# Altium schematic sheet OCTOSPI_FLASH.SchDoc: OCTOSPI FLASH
size A4; Date: Not used; ApprovedBy: Not used; CheckedBy: Not used; Author: Not used; CompanyName: STMicroelectronics; DrawnBy: Not used; Engineer: Not used; Organization: Not used; Address1: Not used; Address2: Not used; Address3: Not used; Address4: Not used; DocumentNumber: Not used; Revision: Not used; SheetNumber: 6; SheetTotal: 16
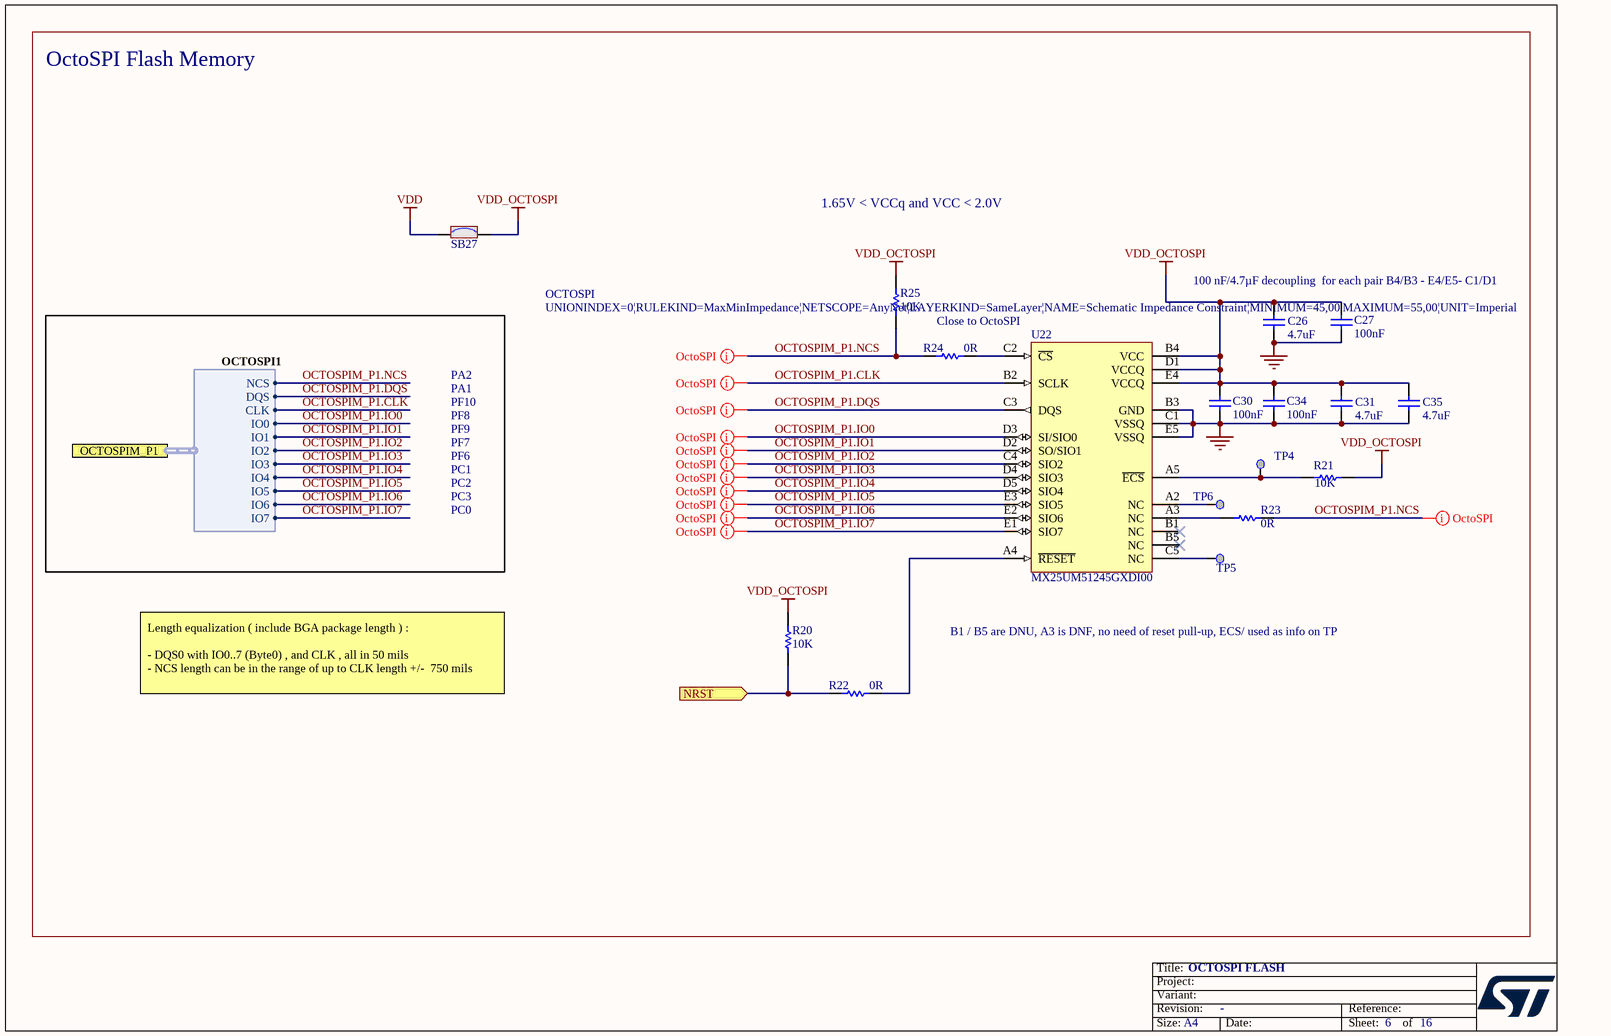
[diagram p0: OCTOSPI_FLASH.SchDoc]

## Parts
C26  value 4.7uF  [C0603]  (hidden comment: Capacitor)
C27  value 100nF  [C0402]  (hidden comment: Capacitor)
C30  value 100nF  [C0402]  (hidden comment: Capacitor)
C31  value 4.7uF  [C0603]  (hidden comment: Capacitor)
C34  value 100nF  [C0402]  (hidden comment: Capacitor)
C35  value 4.7uF  [C0603]  (hidden comment: Capacitor)
R20  value 10K  [R0402]  (hidden comment: Resistor)
R21  value 10K  [R0402]  (hidden comment: Resistor)
R22  value 0R  [R0402]  (hidden comment: Resistor)
R23  value 0R  [R0402]  (hidden comment: Resistor)
R24  value 0R  [R0402]  (hidden comment: Resistor)
R25  value 10K  [R0402]  (hidden comment: Resistor)
SB27  SB_ON  [SOLDER-BRIDGE_R0402-0R]  (value not drawn)
TP4  Test Point  [TP_SMD_1MM]  (value not drawn)  (no BOM)
TP5  Test Point  [TP_SMD_1MM]  (value not drawn)  (no BOM)
TP6  Test Point  [TP_SMD_1MM]  (value not drawn)  (no BOM)
U22  value MX25UM51245GXDI00  [ICC_BGA24_5X5-BALL-ARRAY_6X8_P1]  (hidden comment: MX25xx51245GXDx00)

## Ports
NRST (in), OCTOSPIM_P1 (harness OCTOSPI1)

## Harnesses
OCTOSPI1: IO1, IO0, CLK, NCS, IO2, IO3, IO5, IO4, IO6, IO7, DQS

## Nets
GND: C26.1 C27.1 C30.1 C31.1 C34.1 C35.1 U22.B3(GND) U22.C1(VSSQ) U22.E5(VSSQ)
VDD: SB27.1
VDD_OCTOSPI: C26.2 C27.2 C30.2 C31.2 C34.2 C35.2 R20.2 R21.2 R25.2 SB27.2 U22.B4(VCC) U22.D1(VCCQ) U22.E4(VCCQ)
NRST: R20.1 R22.1 ; port NRST
OCTOSPIM_P1.CLK: U22.B2(SCLK) ; port OCTOSPIM_P1.CLK
OCTOSPIM_P1.DQS: U22.C3(DQS) ; port OCTOSPIM_P1.DQS
OCTOSPIM_P1.IO0: U22.D3(SI/SIO0) ; port OCTOSPIM_P1.IO0
OCTOSPIM_P1.IO1: U22.D2(SO/SIO1) ; port OCTOSPIM_P1.IO1
OCTOSPIM_P1.IO2: U22.C4(SIO2) ; port OCTOSPIM_P1.IO2
OCTOSPIM_P1.IO3: U22.D4(SIO3) ; port OCTOSPIM_P1.IO3
OCTOSPIM_P1.IO4: U22.D5(SIO4) ; port OCTOSPIM_P1.IO4
OCTOSPIM_P1.IO5: U22.E3(SIO5) ; port OCTOSPIM_P1.IO5
OCTOSPIM_P1.IO6: U22.E2(SIO6) ; port OCTOSPIM_P1.IO6
OCTOSPIM_P1.IO7: U22.E1(SIO7) ; port OCTOSPIM_P1.IO7
OCTOSPIM_P1.NCS: R23.2 R24.1 R25.1 ; port OCTOSPIM_P1.NCS
NetR21_1: R21.1 TP4.1 U22.A5(~{ECS})
NetR22_2: R22.2 U22.A4(~{RESET})
NetR23_1: R23.1 U22.A3(NC)
NetR24_2: R24.2 U22.C2(~{CS})
NetTP5_1: TP5.1 U22.C5(NC)
NetTP6_1: TP6.1 U22.A2(NC)

Not connected (* = marked no-connect by the designer): U22 B1(NC)* B5(NC)*

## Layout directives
rule Matched Net Lengths [Tolerance = 1000mil]; net class OCTOSPI; rule Impedance Constraint [Min = 45.00    Max = 55.00    ]; rule Routing Layers [TopLayer - Enabled BottomLayer - Disabled]: OCTOSPIM_P1.NCS
rule Matched Net Lengths [Tolerance = 10mil]; net class OCTOSPI; rule Impedance Constraint [Min = 45.00    Max = 55.00    ]; rule Routing Layers [TopLayer - Enabled BottomLayer - Disabled]: OCTOSPIM_P1.CLK
rule Matched Net Lengths [Tolerance = 20mil]; net class OCTOSPI; rule Impedance Constraint [Min = 45.00    Max = 55.00    ]; rule Routing Layers [TopLayer - Enabled BottomLayer - Disabled]: OCTOSPIM_P1.DQS, OCTOSPIM_P1.IO0, OCTOSPIM_P1.IO1, OCTOSPIM_P1.IO2, OCTOSPIM_P1.IO3, OCTOSPIM_P1.IO4, OCTOSPIM_P1.IO5, OCTOSPIM_P1.IO6, OCTOSPIM_P1.IO7
rule Matched Net Lengths [Tolerance = 500mil]; net class OCTOSPI; rule Impedance Constraint [Min = 45.00    Max = 55.00    ]; rule Routing Layers [TopLayer - Enabled BottomLayer - Disabled]: OCTOSPIM_P1.NCS

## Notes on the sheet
- OctoSPI Flash Memory
- 1.65V < VCCq and VCC < 2.0V
- 100 nF/4.7µF decoupling  for each pair B4/B3 - E4/E5- C1/D1
- PA2
- Close to OctoSPI
- PF7
- PF9
- PF8
- PF10
- PA1
- PC0
- PC1
- PC3
- PC2
- PF6
- B1 / B5 are DNU, A3 is DNF, no need of reset pull-up, ECS/ used as info on TP
- Length equalization ( include BGA package length ) :
  - DQS0 with IO0..7 (Byte0) , and CLK , all in 50 mils
  - NCS length can be in the range of up to CLK length +/-  750 mils

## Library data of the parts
C26 C31 C35 = MCD-00009: Capacitor, MLCC, 4.7uF, 16V, X5R, +/-10%, 0603, T=0.8mm; Manufacturer_Part_Number: CC0603KRX5R7BB475; Manufacturer: YAGEO; Part_Preference: Recommended; Component_Country_Of_Origin: China
C27 C30 C34 = MCD-00006: Capacitor, MLCC, 100nF, 16V, X7R, +/-10%, 0402, T=0.5mm; Manufacturer_Part_Number: CC0402KRX7R7BB104; Manufacturer: YAGEO; Part_Preference: Recommended; Order_Code_RS: 616-9701; Component_Country_Of_Origin: China
R20 R21 R25 = MCD-00053: Resistor, 10K, 0402, +/-1%, 1/16W; Manufacturer_Part_Number: RC0402FR-0710KL; Manufacturer: YAGEO; BMS_Part_Number: 9131590; Part_Preference: Recommended; Component_Country_Of_Origin: China
R22-R24 = MCD-00052: Resistor, 0R, 0402, +/-5%, 1/16W; Manufacturer_Part_Number: RC0402JR-070RL; Manufacturer: YAGEO; Part_Preference: Recommended; Order_Code_RS: 618-5804; Component_Country_Of_Origin: China
SB27 = MCD-01618: Solder Bridge 0402 ON; Part_Type: Misc; Manufacturer_Part_Number: RC0402JR-070RL; Manufacturer: YAGEO; Part_Preference: Recommended; Order_Code_RS: 618-5804; Component_Country_Of_Origin: China
TP4-TP6 = MCD-00074: Test Point 1mm; Part_Type: Misc; Part_Preference: Recommended
U22 = MCD-02166: Memory,Octo-SPI-NOR,512Mb,x1/x8,133/200MHz,1.8V,DTR,BGA24, CMOS MXSMIO; Part_Type: IC; Manufacturer: MACRONIX; Part_Preference: Recommended; Component_Country_Of_Origin: Unknown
